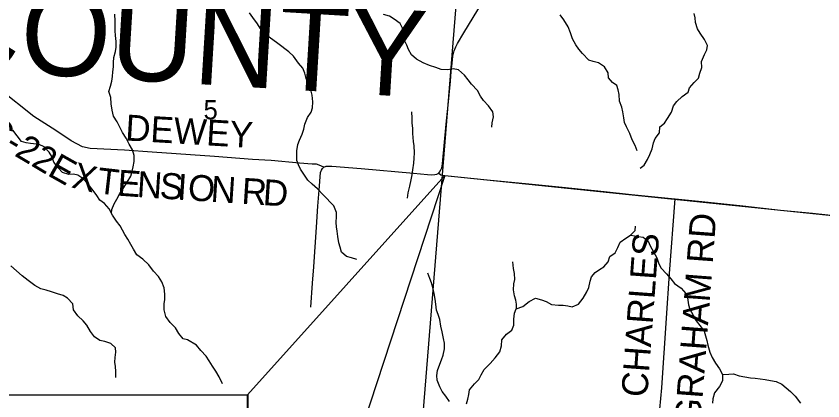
# Model space of a CAD drawing. Extents: x 0 to 40.8, y 0 to 22.
# Drawn here: x 3.414 to 5.177, y 16.222 to 17.063 of the extents above; entities that cross this region are included whole.
import ezdxf

# ---------------------------------------------------------------- set-up
doc = ezdxf.new("R2010")
doc.units = 0
for name, color, linetype in [('Default', 7, 'Continuous'), ('GM_X_County_Road', 7, 'Continuous'), ('GM_X_County_Road_Text', 7, 'Continuous'), ('GM_X_County_Text', 7, 'Continuous'), ('GM_X_Minor_River', 7, 'Continuous'), ('GM_X_Section', 7, 'Continuous'), ('GM_X_Section_Text', 7, 'Continuous'), ('GM_X_State_Route', 7, 'Continuous'), ('GM_X_Township_Road', 7, 'Continuous'), ('GM_X_Township_Road_Text', 7, 'Continuous')]:
    doc.layers.add(name, color=color, linetype=linetype)

msp = doc.modelspace()

# ---------------------------------------------------------------- linework, layer by layer
at = {"layer": 'Default'}
msp.add_lwpolyline([(4.3506, 16.715), (5.2748, 16.619), (5.3265, 16.6142), (5.3792, 16.6434), (5.447, 16.6726), (5.5144, 16.6961), (5.9138, 16.8341), (6.0334, 16.8664), (6.155, 16.8931), (6.2776, 16.9198), (6.5168, 16.9746), (6.7757, 17.0304), (6.8501, 17.0497), (6.8977, 17.0853), (6.8977, 17.0853), (6.9174, 17.1192), (6.9291, 17.1755), (6.9382, 17.2349), (6.9766, 17.6024), (7.3436, 17.5605), (7.48, 17.5474)], dxfattribs=at)
for points in [[(3.9195, 16.2351), (4.3506, 16.715), (3.9199, 15.4019)], [(2.3843, 16.2351), (3.9199, 16.2351), (3.9199, 15.4019), (2.3843, 15.4019)]]:
    msp.add_lwpolyline(points, close=True, dxfattribs=at)
at = {"layer": 'GM_X_County_Road'}
msp.add_lwpolyline([(4.0865, 16.733), (4.0761, 16.7376), (4.0703, 16.7392), (4.0605, 16.7398), (4.0333, 16.7415), (3.9711, 16.7474), (3.9305, 16.7499), (3.8475, 16.7564), (3.7108, 16.7659), (3.6507, 16.7699), (3.5755, 16.7735), (3.559, 16.7776), (3.5345, 16.7905), (3.5009, 16.8134), (3.4526, 16.8435), (3.3767, 16.9038)], dxfattribs=at)
at = {"layer": 'GM_X_Minor_River'}
for points in [[(3.6222, 16.6321), (3.6232, 16.6402), (3.6282, 16.653), (3.6336, 16.6629), (3.6408, 16.6754), (3.6477, 16.6867), (3.6564, 16.7), (3.6648, 16.7136), (3.6675, 16.7239), (3.6698, 16.7337), (3.6717, 16.7451), (3.6718, 16.7584), (3.6684, 16.7705), (3.6608, 16.7835), (3.6544, 16.7964), (3.6465, 16.8089), (3.6401, 16.8222), (3.6344, 16.8321), (3.6269, 16.8447), (3.6235, 16.8572), (3.6213, 16.8716), (3.621, 16.8849), (3.6168, 16.8982), (3.6203, 16.9103), (3.6233, 16.9206), (3.6245, 16.9308), (3.6253, 16.9411), (3.6265, 16.9521), (3.6269, 16.9615), (3.6273, 16.9729), (3.6311, 16.9858), (3.6327, 16.9953), (3.6323, 17.0074), (3.6308, 17.0207), (3.6301, 17.0306), (3.6305, 17.0412), (3.6306, 17.0522), (3.6298, 17.0674)], [(4.1587, 16.5311), (4.1466, 16.5345), (4.1356, 16.5375), (4.125, 16.5474), (4.122, 16.558), (4.1193, 16.5679), (4.1167, 16.5811), (4.1155, 16.5929), (4.1136, 16.6024), (4.1129, 16.6122), (4.1136, 16.6248), (4.1136, 16.6342), (4.1083, 16.6483), (4.0849, 16.6726), (4.0727, 16.6854), (4.0606, 16.6961), (4.0511, 16.7048), (4.0439, 16.7154), (4.0356, 16.7283), (4.0307, 16.7378), (4.0273, 16.7477), (4.0269, 16.7575), (4.0273, 16.7689), (4.0296, 16.7822), (4.0333, 16.792), (4.0387, 16.8049), (4.0424, 16.8163), (4.0451, 16.8269), (4.0508, 16.8417), (4.0584, 16.8535), (4.0618, 16.863), (4.0625, 16.8759), (4.0606, 16.8903), (4.058, 16.902), (4.0523, 16.9168), (4.0474, 16.9267), (4.0444, 16.9385), (4.0402, 16.9491), (4.0311, 16.9605), (4.0201, 16.9753), (4.0095, 16.9851), (3.986, 17.0033), (3.9747, 17.0113), (3.9648, 17.0185), (3.955, 17.0269), (3.9474, 17.0371), (3.9413, 17.0466), (3.9311, 17.0603), (3.9235, 17.0701)], [(4.4535, 16.8201), (4.4539, 16.8299), (4.4569, 16.8432), (4.4554, 16.8538), (4.4459, 16.8671), (4.4353, 16.8789), (4.4285, 16.8883), (4.4221, 16.9005), (4.4088, 16.9141), (4.4016, 16.9236), (4.3937, 16.9339), (4.3808, 16.9456), (4.3687, 16.9479), (4.3562, 16.946), (4.3425, 16.9468), (4.3308, 16.9506), (4.3171, 16.9551), (4.3031, 16.9608), (4.2891, 16.9688), (4.2777, 16.9783), (4.2713, 16.9904), (4.2675, 16.9999), (4.2618, 17.0113), (4.2592, 17.0234), (4.2584, 17.0367), (4.2531, 17.0469), (4.2402, 17.0564), (4.23, 17.0629), (4.2164, 17.0667)], [(4.7706, 16.7684), (4.7665, 16.7806), (4.76, 16.7927), (4.7551, 16.8067), (4.7475, 16.8208), (4.7433, 16.8303), (4.7418, 16.8405), (4.7399, 16.8538), (4.7373, 16.864), (4.7327, 16.8769), (4.7316, 16.8917), (4.7293, 16.902), (4.7263, 16.9118), (4.7168, 16.9183), (4.7085, 16.9285), (4.7074, 16.9388), (4.6998, 16.9524), (4.6865, 16.9608), (4.6748, 16.9638), (4.6653, 16.9665), (4.6513, 16.9816), (4.6437, 16.9911), (4.6369, 17.0006), (4.6293, 17.0135), (4.6256, 17.0264), (4.6199, 17.0397), (4.6108, 17.0549), (4.6024, 17.0659)], [(4.7774, 16.7305), (4.7865, 16.7377), (4.7933, 16.7498), (4.7987, 16.7605), (4.8036, 16.7734), (4.8066, 16.7863), (4.8104, 16.7957), (4.8195, 16.8079), (4.8206, 16.8212), (4.8305, 16.8295), (4.8369, 16.8394), (4.846, 16.853), (4.8502, 16.8667), (4.8578, 16.8762), (4.8691, 16.8875), (4.8824, 16.897), (4.8854, 16.9065), (4.8953, 16.9179), (4.9048, 16.9277), (4.9078, 16.9387), (4.912, 16.9509), (4.9112, 16.9642), (4.9184, 16.979), (4.9233, 16.9892), (4.9249, 16.9987), (4.918, 17.012), (4.9086, 17.026), (4.9025, 17.0355), (4.8987, 17.0491), (4.8976, 17.059), (4.8953, 17.0685)], [(4.269, 16.6649), (4.2709, 16.6767), (4.2743, 16.6915), (4.2769, 16.7051), (4.2792, 16.7165), (4.2811, 16.7275), (4.283, 16.7419), (4.2838, 16.7529), (4.2845, 16.7643), (4.2834, 16.7799), (4.2823, 16.7894), (4.2811, 16.8064), (4.2804, 16.8174), (4.2796, 16.8299), (4.2796, 16.8402), (4.2785, 16.8542)], [(3.7885, 16.3554), (3.779, 16.3577), (3.7692, 16.3691), (3.7624, 16.382), (3.7507, 16.3938), (3.7409, 16.4064), (3.7375, 16.4208), (3.7375, 16.4341), (3.7391, 16.4436), (3.7391, 16.4554), (3.7376, 16.469), (3.732, 16.4823), (3.7248, 16.4941), (3.7142, 16.5059), (3.704, 16.5192), (3.6908, 16.5318), (3.6779, 16.5413), (3.67, 16.5539), (3.6644, 16.5638), (3.6579, 16.5759), (3.6515, 16.5858), (3.641, 16.6048), (3.633, 16.6147), (3.6244, 16.628), (3.6172, 16.6417), (3.607, 16.6535), (3.5971, 16.6611), (3.5903, 16.671), (3.582, 16.6817), (3.5715, 16.6957), (3.5597, 16.7083), (3.5484, 16.7156), (3.5389, 16.7175), (3.5287, 16.7171), (3.5154, 16.721), (3.5056, 16.7313), (3.4961, 16.7442), (3.492, 16.7564), (3.4863, 16.7659), (3.475, 16.7777), (3.4644, 16.7826), (3.4454, 16.785), (3.4356, 16.7858), (3.4257, 16.7888), (3.4159, 16.8018), (3.4068, 16.8136)], [(4.5012, 16.388), (4.5012, 16.4005), (4.5031, 16.4138), (4.5069, 16.4233), (4.5209, 16.4282), (4.5349, 16.4396), (4.5485, 16.4464), (4.5622, 16.443), (4.5724, 16.4392), (4.5834, 16.4328), (4.5993, 16.4312), (4.6095, 16.4312), (4.6198, 16.4297), (4.6292, 16.4274), (4.6425, 16.4335), (4.6527, 16.4464), (4.6611, 16.4604), (4.6652, 16.4699), (4.6679, 16.4836), (4.6713, 16.4931), (4.6789, 16.5025), (4.6884, 16.509), (4.6982, 16.5151), (4.7073, 16.5264), (4.7115, 16.5378), (4.7228, 16.5458), (4.7289, 16.5572), (4.7338, 16.5693), (4.746, 16.578), (4.7562, 16.5841), (4.7664, 16.5943), (4.7676, 16.6042)], [(4.7568, 16.5846), (4.7729, 16.5814), (4.7838, 16.5799), (4.7952, 16.5712), (4.7994, 16.5613), (4.8066, 16.5477), (4.8138, 16.5351), (4.8183, 16.5219), (4.8232, 16.512), (4.835, 16.4999), (4.8448, 16.4889), (4.8528, 16.4786), (4.8668, 16.4684), (4.8774, 16.4566), (4.8812, 16.4471), (4.8831, 16.432), (4.8861, 16.4225), (4.8933, 16.4092), (4.8997, 16.3974), (4.9077, 16.3868), (4.9172, 16.3743), (4.9206, 16.3641), (4.9229, 16.3542), (4.9251, 16.3436), (4.93, 16.3284), (4.9346, 16.317), (4.9418, 16.3045), (4.9509, 16.292), (4.9577, 16.2795), (4.9573, 16.2662), (4.9509, 16.2533), (4.9399, 16.24), (4.9361, 16.2267), (4.9353, 16.2169)], [(4.5073, 16.4234), (4.5072, 16.4332), (4.5057, 16.4426), (4.5027, 16.4521), (4.5008, 16.4646), (4.5016, 16.4779), (4.5038, 16.4874), (4.5027, 16.5007), (4.5008, 16.5117), (4.4993, 16.5258)], [(3.6316, 16.2736), (3.632, 16.2861), (3.6309, 16.2975), (3.6298, 16.307), (3.6302, 16.3169), (3.6314, 16.3286), (3.6307, 16.3381), (3.6209, 16.3476), (3.6076, 16.3522), (3.597, 16.3538), (3.5852, 16.3622), (3.5762, 16.374), (3.5683, 16.3873), (3.5607, 16.3968), (3.5486, 16.4082), (3.5392, 16.4215), (3.5381, 16.4344), (3.5263, 16.447), (3.5165, 16.4523), (3.504, 16.4562), (3.4911, 16.4604), (3.4797, 16.4639), (3.468, 16.4673), (3.4551, 16.4746), (3.4404, 16.4849), (3.4271, 16.4952), (3.4146, 16.5062), (3.4025, 16.5172)], [(4.361, 16.2211), (4.3526, 16.2325), (4.3451, 16.2424), (4.3394, 16.253), (4.3341, 16.2674), (4.3329, 16.2773), (4.3348, 16.2883), (4.3394, 16.3027), (4.3432, 16.3122), (4.3473, 16.322), (4.35, 16.3357), (4.35, 16.3482), (4.3481, 16.3588), (4.3451, 16.3729), (4.3421, 16.3858), (4.3394, 16.3998), (4.336, 16.4108), (4.3326, 16.4207), (4.3307, 16.4332), (4.3292, 16.4446), (4.3277, 16.4567), (4.325, 16.4673), (4.3212, 16.4798), (4.3182, 16.4893), (4.3137, 16.5015)], [(4.3981, 16.2154), (4.4007, 16.2257), (4.403, 16.2359), (4.4045, 16.2462), (4.4152, 16.2594), (4.4246, 16.2689), (4.4303, 16.2792), (4.4368, 16.2909), (4.4496, 16.3042), (4.461, 16.3163), (4.4705, 16.3296), (4.4746, 16.3425), (4.475, 16.3558), (4.4853, 16.3679), (4.4974, 16.377), (4.5012, 16.388)], [(3.865, 16.2595), (3.8578, 16.2747), (3.8506, 16.2868), (3.8427, 16.2982), (3.8355, 16.3096), (3.8291, 16.3198), (3.8177, 16.3323), (3.8078, 16.3437), (3.7885, 16.3554)], [(4.9577, 16.2795), (4.971, 16.2806), (4.9812, 16.2814), (4.9937, 16.2772), (5.0062, 16.2745), (5.0187, 16.2723), (5.0285, 16.2715), (5.0395, 16.2704), (5.0509, 16.2688), (5.0623, 16.2669), (5.0748, 16.2643), (5.0869, 16.2586), (5.0967, 16.251), (5.1062, 16.2427), (5.1164, 16.2324), (5.1282, 16.2172)]]:
    msp.add_lwpolyline(points, dxfattribs=at)
at = {"layer": 'GM_X_Section'}
msp.add_lwpolyline([(3.2542, 16.2539), (3.3398, 17.3372), (3.4517, 17.3312), (4.3898, 17.2759), (4.2989, 16.1489), (3.9097, 16.1796)], dxfattribs=at)
at = {"layer": 'GM_X_State_Route'}
for points in [[(4.3372, 16.7202), (4.3393, 16.7224), (4.342, 16.7268), (4.3441, 16.7314), (4.3455, 16.74), (4.3539, 16.8267), (4.3577, 16.8686), (4.3632, 16.9206), (4.3648, 16.9424), (4.3665, 16.9606), (4.3683, 16.9753), (4.3711, 16.987), (4.3745, 16.9957), (4.3786, 17.0031), (4.3919, 17.0267), (4.4431, 17.1112), (4.4815, 17.1754), (4.5035, 17.2134), (4.5266, 17.2521), (4.535, 17.2682)], [(4.0575, 16.4269), (4.0616, 16.4795), (4.0642, 16.5152), (4.07, 16.6015), (4.0735, 16.648), (4.076, 16.683), (4.0789, 16.7213), (4.081, 16.7263), (4.0831, 16.7297), (4.0865, 16.733), (4.091, 16.735), (4.0933, 16.7353), (4.0975, 16.7355), (4.1038, 16.7349), (4.1676, 16.7301), (4.2825, 16.72), (4.3125, 16.7173), (4.3216, 16.7165), (4.329, 16.7166), (4.3334, 16.7178), (4.3372, 16.7202)], [(4.3372, 16.7202), (4.3416, 16.7164), (4.3506, 16.715), (4.443, 16.7056), (4.5344, 16.6963), (4.6072, 16.6892), (4.6985, 16.6795), (4.7586, 16.6732), (4.8387, 16.6653), (4.8543, 16.6637), (4.9122, 16.6578), (5.002, 16.6483), (5.0839, 16.6393), (5.1541, 16.6323), (5.2209, 16.625)]]:
    msp.add_lwpolyline(points, dxfattribs=at)
at = {"layer": 'GM_X_Township_Road'}
msp.add_lwpolyline([(4.7567, 15.9814), (4.8734, 16.0508), (4.9218, 16.131), (4.896, 16.1415), (4.8688, 16.1562), (4.8579, 16.1607), (4.846, 16.1623), (4.8378, 16.1635), (4.8263, 16.163), (4.8218, 16.1673), (4.8186, 16.1737), (4.8202, 16.2039), (4.825, 16.2508), (4.8353, 16.4031), (4.8419, 16.5006), (4.8543, 16.6637)], dxfattribs=at)

# ---------------------------------------------------------------- texts
at = {"layer": 'GM_X_County_Road_Text'}
for s, height, rotation, p in [('C-22', 0.05682, 329.154, (3.3394, 16.8002)), ('DEWEY', 0.05682, 356.5775, (3.6514, 16.7914)), ('E', 0.0568, 330.6107, (3.4799, 16.7162)), ('X', 0.0568, 346.4354, (3.5328, 16.6891)), ('T', 0.0568, 353.4618, (3.5889, 16.6761)), ('E', 0.0568, 355.8411, (3.6337, 16.671)), ('N', 0.0568, 356.3069, (3.6766, 16.6679)), ('S', 0.0568, 356.3305, (3.7265, 16.6647)), ('I', 0.0568, 356.3287, (3.7647, 16.6622)), ('O', 0.0568, 356.3294, (3.788, 16.6607)), ('N', 0.0568, 356.3294, (3.8379, 16.6575)), ('R', 0.0568, 356.3287, (3.9053, 16.6532)), ('D', 0.0568, 356.3313, (3.9519, 16.6502))]:
    msp.add_text(s, height=height, rotation=rotation, dxfattribs=at).set_placement(p)
at = {"layer": 'GM_X_County_Text'}
msp.add_text('SCIOTO COUNTY', height=0.189394, rotation=356.5147, dxfattribs=at).set_placement((2.1971, 17.0129))
at = {"layer": 'GM_X_Section_Text'}
msp.add_text('5', height=0.0419, rotation=0, dxfattribs=at).set_placement((3.8234, 16.8376))
at = {"layer": 'GM_X_Township_Road_Text'}
for s, rotation, p in [('GRAHAM RD', 85.7054, (4.9093, 16.1675)), ('CHARLES', 85.7748, (4.7928, 16.2291))]:
    msp.add_text(s, height=0.05682, rotation=rotation, dxfattribs=at).set_placement(p)

doc.saveas('drawing.dxf')
